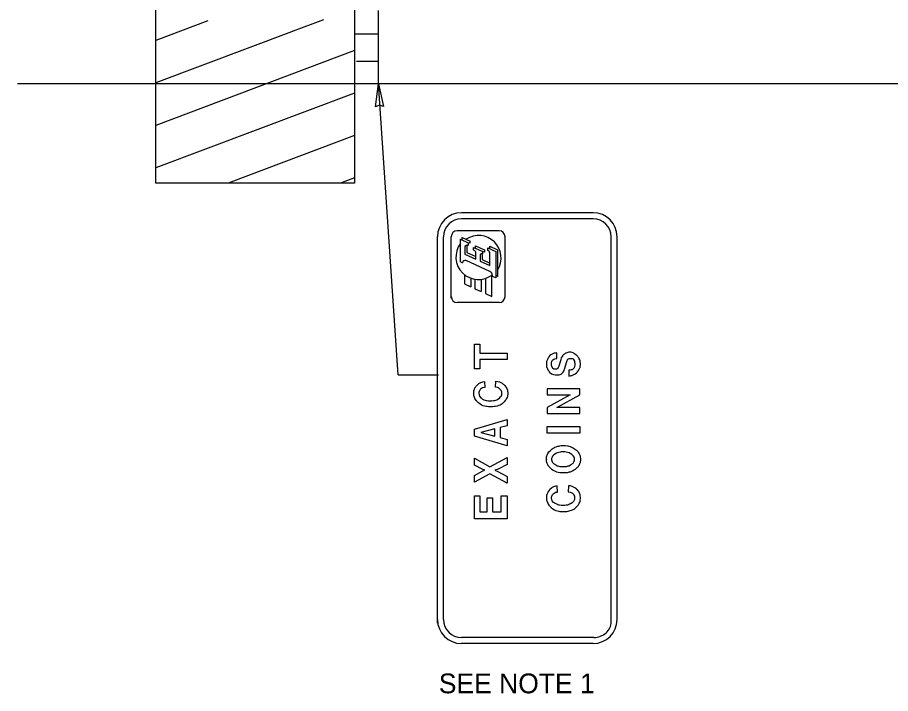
# Model space of a CAD drawing. Extents: x 46672 to 47298, y 5424 to 5829.
# Drawn here: x 47015.3 to 47138.8, y 5542.3 to 5638 of the extents above; entities that cross this region are included whole.
import ezdxf

# ---------------------------------------------------------------- set-up
doc = ezdxf.new("R2010")
doc.units = 0
for name, color, linetype in [('LeaderLine_dp', 7, 'Continuous'), ('RoadwayMisc', 7, 'Continuous'), ('SignSupport', 7, 'Continuous'), ('TextLabel', 7, 'Continuous'), ('TextShtNo', 7, 'Continuous')]:
    doc.layers.add(name, color=color, linetype=linetype)

msp = doc.modelspace()

# ---------------------------------------------------------------- linework, layer by layer
at = {"layer": 'LeaderLine_dp'}
for q in [(47066.34, 5628.63), (47074.84, 5587.4)]:
    msp.add_line((47069.16, 5587.41), q, dxfattribs=at)
msp.add_lwpolyline([(47066.34, 5628.63), (47067.08, 5625.39), (47066.5, 5625.6), (47065.93, 5625.34)], close=True, dxfattribs=at)
at = {"layer": 'RoadwayMisc'}
for p, q in [((47034.83, 5614.56), (47034.83, 5668.42)), ((47062.95, 5668.42), (47062.96, 5614.56)), ((47058.59, 5637.7), (47053.88, 5635.93)), ((47042.18, 5637.53), (47034.83, 5634.75)), ((47054.42, 5636.13), (47034.83, 5628.74)), ((47062.95, 5633.34), (47034.83, 5622.73)), ((47285.32, 5628.64), (47015.26, 5628.64)), ((47062.96, 5627.32), (47034.83, 5616.72)), ((47062.96, 5621.31), (47045.06, 5614.56)), ((47062.96, 5614.56), (47034.83, 5614.56)), ((47062.96, 5615.3), (47061, 5614.56))]:
    msp.add_line(p, q, dxfattribs=at)
at = {"layer": 'SignSupport'}
for p, q in [((47066.34, 5628.63), (47066.34, 5639.02)), ((47063, 5635.7), (47066.34, 5635.7)), ((47063.22, 5631.85), (47066.34, 5631.85))]:
    msp.add_line(p, q, dxfattribs=at)
at = {"layer": 'TextShtNo'}
for p, q in [((47096.73, 5610.35), (47078.09, 5610.35)), ((47096.73, 5609.51), (47078.09, 5609.51)), ((47074.71, 5552.26), (47074.71, 5606.97)), ((47075.55, 5552.76), (47075.55, 5606.97)), ((47076.64, 5598.26), (47076.64, 5606.97)), ((47083.42, 5607.81), (47077.49, 5607.81)), ((47078.21, 5606.52), (47078.21, 5606.87)), ((47078.21, 5606.87), (47079.33, 5606.36)), ((47084.26, 5598.5), (47084.26, 5606.97)), ((47099.27, 5552.44), (47099.27, 5606.97)), ((47100.12, 5552.76), (47100.12, 5606.97)), ((47077.95, 5603.43), (47077.95, 5606.64)), ((47077.95, 5606.64), (47079.06, 5606.12)), ((47078.84, 5605.77), (47078.84, 5604.75)), ((47079.06, 5606.12), (47079.06, 5605.75)), ((47079.33, 5606.05), (47079.33, 5606.36)), ((47080.06, 5605.34), (47080.06, 5605.7)), ((47080.06, 5605.7), (47081.36, 5605.1)), ((47082.09, 5605.29), (47082.09, 5605.65)), ((47082.09, 5605.65), (47083.21, 5605.13)), ((47078.57, 5605.48), (47078.57, 5604.52)), ((47078.57, 5604.52), (47080.13, 5603.8)), ((47078.84, 5604.75), (47080.13, 5604.15)), ((47079.8, 5605.09), (47079.8, 5605.46)), ((47079.8, 5605.46), (47081.1, 5604.87)), ((47079.8, 5605.09), (47079.91, 5605.04)), ((47080.13, 5603.8), (47080.13, 5604.7)), ((47080.76, 5604.38), (47080.76, 5603.51)), ((47081.02, 5604.57), (47081.02, 5603.74)), ((47081.1, 5604.55), (47081.1, 5604.87)), ((47081.36, 5605.1), (47081.36, 5604.79)), ((47081.83, 5605.03), (47081.83, 5605.41)), ((47081.83, 5605.41), (47082.94, 5604.9)), ((47082.11, 5602.88), (47082.11, 5604.62)), ((47082.94, 5604.9), (47082.94, 5601.13)), ((47083.21, 5605.13), (47083.21, 5601.36)), ((47077.95, 5603.43), (47078.26, 5603.29)), ((47082.12, 5602.04), (47078.77, 5603.58)), ((47080.76, 5603.51), (47082.11, 5602.88)), ((47081.02, 5603.74), (47082.11, 5603.24)), ((47078.52, 5601.6), (47078.52, 5600.29)), ((47079.4, 5601.11), (47079.4, 5599.88)), ((47080.01, 5600.95), (47080.01, 5599.6)), ((47080.88, 5600.93), (47080.88, 5599.2)), ((47081.5, 5601.07), (47081.5, 5598.91)), ((47082.37, 5598.51), (47082.37, 5601.52)), ((47082.48, 5601.34), (47082.48, 5601.5)), ((47082.94, 5601.13), (47082.48, 5601.34)), ((47083.21, 5601.36), (47082.94, 5601.48)), ((47078.52, 5600.29), (47079.4, 5599.88)), ((47080.01, 5599.6), (47080.88, 5599.2)), ((47081.5, 5598.91), (47082.37, 5598.51)), ((47083.42, 5597.65), (47077.49, 5597.65)), ((47090.12, 5575.45), (47090.12, 5575.42)), ((47096.82, 5550.22), (47078.09, 5550.22)), ((47096.73, 5549.37), (47078.09, 5549.37))]:
    msp.add_line(p, q, dxfattribs=at)
for points in [[(47079.95, 5588.28), (47079.95, 5591.75), (47080.71, 5591.75), (47080.71, 5590.46), (47084.57, 5590.46), (47084.57, 5589.57), (47080.71, 5589.57), (47080.71, 5588.28), (47079.95, 5588.28)], [(47090.48, 5589.96), (47090.4, 5589.86), (47090.37, 5589.8), (47090.3, 5589.66), (47090.22, 5589.5), (47090.19, 5589.4), (47090.15, 5589.3), (47090.11, 5589.03), (47090.11, 5588.9), (47090.11, 5588.83), (47090.15, 5588.6), (47090.19, 5588.46), (47090.26, 5588.26), (47090.33, 5588.13), (47090.37, 5588.06), (47090.44, 5587.96), (47090.51, 5587.86)], [(47091.6, 5589.73), (47091.57, 5590.53), (47091.39, 5590.5), (47091.2, 5590.46), (47091.02, 5590.4), (47090.91, 5590.33), (47090.73, 5590.23), (47090.62, 5590.13), (47090.48, 5589.96)], [(47090.51, 5587.86), (47090.62, 5587.73), (47090.84, 5587.56), (47091.1, 5587.46), (47091.39, 5587.4), (47091.71, 5587.4), (47091.93, 5587.43), (47092.19, 5587.53), (47092.33, 5587.66), (47092.48, 5587.8), (47092.62, 5588.03), (47092.69, 5588.23), (47092.99, 5589.3), (47093.06, 5589.46), (47093.17, 5589.63), (47093.35, 5589.73), (47093.53, 5589.73), (47093.64, 5589.73)], [(47091.42, 5588.2), (47091.31, 5588.2), (47091.17, 5588.23), (47091.06, 5588.33), (47090.95, 5588.5), (47090.88, 5588.63), (47090.84, 5588.73), (47090.84, 5588.9), (47090.84, 5589.1), (47090.88, 5589.3), (47090.95, 5589.43), (47091.02, 5589.53), (47091.17, 5589.63), (47091.31, 5589.7), (47091.6, 5589.73)], [(47093.93, 5590.5), (47093.89, 5590.53), (47093.75, 5590.56), (47093.57, 5590.6), (47093.39, 5590.6), (47093.28, 5590.6), (47093.13, 5590.56), (47092.91, 5590.5), (47092.8, 5590.46), (47092.66, 5590.36), (47092.51, 5590.26), (47092.44, 5590.16), (47092.33, 5590.03), (47092.22, 5589.83), (47092.15, 5589.56), (47092.11, 5589.4), (47091.89, 5588.66), (47091.79, 5588.43), (47091.71, 5588.33), (47091.64, 5588.26), (47091.53, 5588.2), (47091.42, 5588.2)], [(47093.31, 5587.23), (47093.46, 5587.26), (47093.6, 5587.3), (47093.75, 5587.33), (47093.82, 5587.36), (47093.89, 5587.4), (47094, 5587.46), (47094.15, 5587.53), (47094.18, 5587.56), (47094.37, 5587.7), (47094.51, 5587.86), (47094.66, 5588.03), (47094.69, 5588.1), (47094.77, 5588.23), (47094.8, 5588.3), (47094.84, 5588.4), (47094.87, 5588.46), (47094.91, 5588.6), (47094.95, 5588.83), (47094.95, 5588.93), (47094.95, 5589.03), (47094.91, 5589.26), (47094.87, 5589.43), (47094.84, 5589.53), (47094.77, 5589.7), (47094.69, 5589.83), (47094.62, 5589.93), (47094.55, 5590.03), (47094.48, 5590.1), (47094.37, 5590.2), (47094.29, 5590.26), (47094.15, 5590.36), (47094.04, 5590.43), (47093.93, 5590.5)], [(47093.64, 5589.73), (47093.75, 5589.73), (47093.89, 5589.66), (47093.97, 5589.6), (47094.08, 5589.36)], [(47094.08, 5589.36), (47094.11, 5589.23), (47094.15, 5589.06), (47094.15, 5588.9), (47094.15, 5588.8), (47094.11, 5588.6), (47094.04, 5588.4), (47093.97, 5588.3), (47093.86, 5588.2), (47093.75, 5588.13), (47093.64, 5588.1), (47093.49, 5588.06), (47093.39, 5588.06)], [(47093.39, 5588.06), (47093.28, 5588.06), (47093.31, 5587.23)], [(47082.95, 5586.5), (47083.24, 5586.47), (47083.46, 5586.4), (47083.68, 5586.31), (47083.86, 5586.21), (47084.01, 5586.11), (47084.08, 5586.04), (47084.15, 5585.98), (47084.23, 5585.91), (47084.33, 5585.78), (47084.41, 5585.68), (47084.44, 5585.61), (47084.52, 5585.48), (47084.55, 5585.38), (47084.59, 5585.25), (47084.63, 5585.12), (47084.66, 5584.85), (47084.66, 5584.69), (47084.63, 5584.42), (47084.59, 5584.32), (47084.55, 5584.19), (47084.48, 5584.06), (47084.41, 5583.93), (47084.37, 5583.86), (47084.3, 5583.76), (47084.15, 5583.6), (47084.01, 5583.47), (47083.86, 5583.33), (47083.72, 5583.23), (47083.53, 5583.14), (47083.39, 5583.07), (47083.17, 5583), (47082.92, 5582.94), (47082.74, 5582.91), (47082.48, 5582.87), (47082.15, 5582.87), (47081.9, 5582.87), (47081.72, 5582.91), (47081.57, 5582.94), (47081.39, 5582.97), (47081.17, 5583.04), (47080.95, 5583.14), (47080.74, 5583.27), (47080.52, 5583.43), (47080.3, 5583.63), (47080.19, 5583.76), (47080.08, 5583.93), (47080.01, 5584.06), (47079.9, 5584.36), (47079.86, 5584.49), (47079.83, 5584.75), (47079.83, 5584.89), (47079.86, 5585.15), (47079.9, 5585.28), (47079.94, 5585.38), (47080.01, 5585.55), (47080.08, 5585.68), (47080.15, 5585.78), (47080.26, 5585.91), (47080.37, 5586.01), (47080.55, 5586.17), (47080.66, 5586.24), (47080.85, 5586.34), (47081.1, 5586.44), (47081.35, 5586.47)], [(47081.35, 5586.47), (47081.39, 5585.61)], [(47082.92, 5585.65), (47082.95, 5586.5)], [(47081.39, 5585.61), (47081.14, 5585.58), (47081.06, 5585.55), (47080.92, 5585.48), (47080.81, 5585.38), (47080.74, 5585.31), (47080.7, 5585.25), (47080.63, 5585.15), (47080.59, 5585.05), (47080.55, 5584.92), (47080.55, 5584.82), (47080.59, 5584.56), (47080.66, 5584.39), (47080.85, 5584.16), (47080.92, 5584.09), (47081.06, 5583.99), (47081.28, 5583.89), (47081.43, 5583.83), (47081.57, 5583.8), (47081.68, 5583.76), (47081.9, 5583.73), (47082.08, 5583.73), (47082.12, 5583.73), (47082.3, 5583.73), (47082.41, 5583.73), (47082.63, 5583.76), (47082.81, 5583.8), (47082.95, 5583.83), (47083.1, 5583.89), (47083.24, 5583.96), (47083.46, 5584.09), (47083.64, 5584.29), (47083.75, 5584.46), (47083.79, 5584.56), (47083.83, 5584.75), (47083.83, 5584.85), (47083.79, 5585.02), (47083.72, 5585.18), (47083.64, 5585.31), (47083.5, 5585.45), (47083.35, 5585.55), (47083.21, 5585.61), (47082.92, 5585.65)], [(47090.22, 5581.93), (47094.84, 5581.93), (47094.84, 5582.8), (47091.97, 5582.8), (47091.6, 5582.77), (47094.84, 5584.57), (47094.84, 5585.43), (47090.22, 5585.43), (47090.22, 5584.57), (47092.95, 5584.57), (47093.46, 5584.6), (47090.22, 5582.8), (47090.22, 5581.93)], [(47084.57, 5577.36), (47079.95, 5578.75), (47079.95, 5579.71), (47084.57, 5581.09), (47084.57, 5580.2), (47083.59, 5579.97), (47083.59, 5578.52), (47084.57, 5578.26), (47084.57, 5577.36)], [(47080.82, 5579.25), (47082.82, 5578.72), (47082.82, 5579.77), (47080.82, 5579.25)], [(47094.83, 5579.14), (47090.22, 5579.14), (47090.22, 5580.08), (47094.83, 5580.08), (47094.83, 5579.14)], [(47090.12, 5575.42), (47090.12, 5575.59), (47090.15, 5575.82), (47090.19, 5575.95), (47090.23, 5576.05), (47090.33, 5576.29), (47090.48, 5576.49), (47090.63, 5576.65), (47090.84, 5576.85), (47090.95, 5576.95), (47091.06, 5577.02), (47091.21, 5577.09), (47091.32, 5577.15), (47091.5, 5577.22), (47091.72, 5577.29), (47091.86, 5577.32), (47092.01, 5577.35), (47092.22, 5577.39), (47092.33, 5577.39), (47092.55, 5577.39)], [(47092.55, 5577.39), (47092.81, 5577.39), (47093.13, 5577.35), (47093.28, 5577.32), (47093.46, 5577.25), (47093.68, 5577.19), (47093.82, 5577.12), (47093.93, 5577.05), (47094.11, 5576.95), (47094.22, 5576.85), (47094.37, 5576.75), (47094.51, 5576.59), (47094.59, 5576.49), (47094.66, 5576.39), (47094.77, 5576.22), (47094.84, 5576.05), (47094.88, 5575.95), (47094.91, 5575.75), (47094.95, 5575.55), (47094.95, 5575.49), (47094.95, 5575.32), (47094.91, 5575.09), (47094.88, 5574.99), (47094.84, 5574.85), (47094.81, 5574.79), (47094.77, 5574.69), (47094.73, 5574.62), (47094.66, 5574.52), (47094.55, 5574.35), (47094.48, 5574.28), (47094.19, 5574.02), (47094.11, 5573.95), (47093.93, 5573.85), (47093.82, 5573.79), (47093.68, 5573.72), (47093.46, 5573.65), (47093.35, 5573.62), (47093.21, 5573.58), (47093.06, 5573.55), (47092.84, 5573.52), (47092.66, 5573.52), (47092.55, 5573.52)], [(47092.48, 5576.49), (47092.41, 5576.49), (47092.22, 5576.49), (47092.04, 5576.45), (47091.86, 5576.42), (47091.64, 5576.35), (47091.46, 5576.29), (47091.24, 5576.15), (47091.13, 5576.05), (47090.99, 5575.89), (47090.92, 5575.75), (47090.88, 5575.65), (47090.84, 5575.55), (47090.84, 5575.49), (47090.84, 5575.39), (47090.88, 5575.25), (47090.95, 5575.09), (47091.03, 5574.99), (47091.06, 5574.92), (47091.13, 5574.85), (47091.21, 5574.79), (47091.24, 5574.75), (47091.43, 5574.65), (47091.61, 5574.55), (47091.75, 5574.52), (47091.86, 5574.49), (47092.01, 5574.45), (47092.15, 5574.42), (47092.26, 5574.42), (47092.41, 5574.42), (47092.48, 5574.42)], [(47094.11, 5575.49), (47094.11, 5575.55), (47094.08, 5575.65), (47094.04, 5575.75), (47093.97, 5575.89), (47093.82, 5576.05), (47093.71, 5576.15), (47093.5, 5576.29), (47093.32, 5576.35), (47093.1, 5576.42), (47092.92, 5576.45), (47092.73, 5576.49), (47092.55, 5576.49), (47092.48, 5576.49)], [(47084.55, 5572.05), (47082.12, 5573.41), (47079.94, 5572.22), (47079.94, 5573.17), (47081.14, 5573.8), (47081.39, 5573.9), (47081.14, 5574), (47079.94, 5574.63), (47079.94, 5575.62), (47082.12, 5574.4), (47084.55, 5575.72), (47084.55, 5574.73), (47083.28, 5574.07), (47082.81, 5573.9), (47083.25, 5573.74), (47084.55, 5573.04), (47084.55, 5572.05)], [(47092.55, 5573.52), (47092.44, 5573.52), (47092.26, 5573.52), (47092.01, 5573.55), (47091.79, 5573.58), (47091.61, 5573.65), (47091.39, 5573.72), (47091.21, 5573.82), (47091.06, 5573.89), (47090.95, 5573.95), (47090.84, 5574.05), (47090.59, 5574.28), (47090.55, 5574.32), (47090.48, 5574.42), (47090.41, 5574.52), (47090.33, 5574.62), (47090.3, 5574.69), (47090.23, 5574.85), (47090.19, 5574.99), (47090.15, 5575.12), (47090.12, 5575.45)], [(47092.48, 5574.42), (47092.55, 5574.42), (47092.7, 5574.42), (47092.81, 5574.42), (47092.95, 5574.45), (47093.1, 5574.49), (47093.21, 5574.52), (47093.35, 5574.55), (47093.53, 5574.65), (47093.71, 5574.75), (47093.75, 5574.79), (47093.82, 5574.85), (47093.9, 5574.92), (47093.93, 5574.99), (47094.01, 5575.09), (47094.08, 5575.25), (47094.11, 5575.39), (47094.11, 5575.49)], [(47091.64, 5571.68), (47091.39, 5571.65), (47091.13, 5571.55), (47090.95, 5571.45), (47090.84, 5571.38), (47090.66, 5571.22), (47090.55, 5571.12), (47090.44, 5570.98), (47090.37, 5570.88), (47090.3, 5570.75), (47090.23, 5570.58), (47090.19, 5570.48), (47090.15, 5570.35), (47090.12, 5570.08), (47090.12, 5569.95), (47090.15, 5569.68), (47090.19, 5569.55), (47090.3, 5569.25), (47090.37, 5569.12), (47090.48, 5568.95), (47090.59, 5568.81), (47090.81, 5568.61), (47091.02, 5568.45), (47091.24, 5568.31), (47091.46, 5568.21), (47091.68, 5568.15), (47091.86, 5568.11), (47092.01, 5568.08), (47092.19, 5568.05), (47092.44, 5568.05), (47092.77, 5568.05), (47093.02, 5568.08), (47093.21, 5568.11), (47093.46, 5568.18), (47093.68, 5568.25), (47093.82, 5568.31), (47094.01, 5568.41), (47094.15, 5568.51), (47094.3, 5568.65), (47094.44, 5568.78), (47094.59, 5568.95), (47094.66, 5569.05), (47094.7, 5569.12), (47094.77, 5569.25), (47094.84, 5569.38), (47094.88, 5569.52), (47094.91, 5569.61), (47094.95, 5569.88), (47094.95, 5570.05), (47094.91, 5570.32), (47094.88, 5570.45), (47094.84, 5570.58), (47094.81, 5570.68), (47094.73, 5570.82), (47094.7, 5570.88), (47094.62, 5570.98), (47094.51, 5571.12), (47094.44, 5571.18), (47094.37, 5571.25), (47094.3, 5571.32), (47094.15, 5571.42), (47093.97, 5571.52), (47093.75, 5571.62), (47093.53, 5571.68), (47093.24, 5571.71)], [(47091.68, 5570.82), (47091.64, 5571.68)], [(47093.24, 5571.71), (47093.21, 5570.85)], [(47084.55, 5567.04), (47079.94, 5567.04), (47079.94, 5570.28), (47080.7, 5570.28), (47080.7, 5568), (47081.72, 5568), (47081.72, 5569.98), (47082.48, 5569.98), (47082.48, 5568), (47083.72, 5568), (47083.72, 5570.28), (47084.55, 5570.28), (47084.55, 5567.04)], [(47093.21, 5570.85), (47093.5, 5570.82), (47093.64, 5570.75), (47093.79, 5570.65), (47093.93, 5570.52), (47094.01, 5570.38), (47094.08, 5570.22), (47094.11, 5570.05), (47094.11, 5569.95), (47094.08, 5569.75), (47094.04, 5569.65), (47093.93, 5569.48), (47093.75, 5569.28), (47093.53, 5569.15), (47093.39, 5569.08), (47093.24, 5569.01), (47093.1, 5568.98), (47092.92, 5568.95), (47092.7, 5568.91), (47092.59, 5568.91), (47092.41, 5568.91), (47092.37, 5568.91), (47092.19, 5568.91), (47091.97, 5568.95), (47091.86, 5568.98), (47091.72, 5569.01), (47091.57, 5569.08), (47091.35, 5569.18), (47091.21, 5569.28), (47091.13, 5569.35), (47090.95, 5569.58), (47090.88, 5569.75), (47090.84, 5570.02), (47090.84, 5570.11), (47090.88, 5570.25), (47090.92, 5570.35), (47090.99, 5570.45), (47091.02, 5570.52), (47091.1, 5570.58), (47091.21, 5570.68), (47091.35, 5570.75), (47091.42, 5570.78), (47091.68, 5570.82)]]:
    msp.add_lwpolyline(points, dxfattribs=at)
for centre, radius, start, end in [((47078.09, 5606.97), 3.39, 90, 180), ((47078.09, 5606.97), 2.54, 90, 180), ((47096.73, 5606.97), 3.39, 360, 90), ((47096.73, 5606.97), 2.54, 360, 90), ((47077.49, 5606.97), 0.847, 90, 180), ((47080.52, 5603.95), 3.19, 328.1578, 123.3171), ((47083.42, 5606.97), 0.847, 360, 90), ((47080.5, 5604.1), 3.19, 142.9547, 308.1763), ((47077.49, 5598.5), 0.847, 180, 270), ((47083.42, 5598.5), 0.847, 270, 360), ((47078.09, 5552.76), 3.39, 180, 270), ((47078.09, 5552.76), 2.54, 180, 270), ((47096.73, 5552.76), 3.39, 270, 360)]:
    msp.add_arc(centre, radius, start, end, dxfattribs=at)
for centre, major_axis, start_param, end_param in [((47078.91, 5605.48), (-0.333, 0), 4.227342, 6.283185), ((47079.17, 5605.78), (-0.333, 0), 4.227342, 5.041732), ((47079.72, 5604.7), (-0.416, 0), 3.141593, 4.241405), ((47080.98, 5604.38), (-0.219, 0), 4.144801, 6.283185), ((47081.2, 5604.52), (-0.333, 0), 4.227342, 5.041732), ((47081.59, 5604.62), (-0.52, 0), 3.141593, 4.232591), ((47078.61, 5603.3), (-0.35, 0), 4.241328, 6.314398), ((47081.81, 5601.5), (-0.666, 0), 3.141593, 4.241135), ((47096.82, 5552.44), (-2.45, 0), 1.570796, 3.141593)]:
    msp.add_ellipse(centre, major_axis=major_axis, ratio=0.906668, start_param=start_param, end_param=end_param, dxfattribs=at)

# ---------------------------------------------------------------- texts
at = {"layer": 'TextLabel'}
msp.add_text('SEE NOTE 1', height=2.8, dxfattribs=at).set_placement((47074.89, 5542.32))

doc.saveas('drawing.dxf')
